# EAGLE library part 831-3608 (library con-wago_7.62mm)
Serie 831, Stiftleiste (für Leiterplatten) mit geraden Einlötstiften / Series 831, Male header (for PCBs) with straight solder pins Polzahl / Pole No.: 8 Bemessungsspannung / Rated Voltage: 630 V Nennstrom / Nominal Current: 41 A Lötstiftlänge: / Solder Pin Length: 4 mm Farbe / Color: lichtgrau / light gray Stand: 01.01.2012. Die jeweils aktuellen Daten zu diesem Artikel finden Sie in unserem Produktkatalog, den Sie unter www.wago.com einsehen können. As of: 01/01/2012. Please find the newest data for this article in our product catalogue, which can be viewed under www.wago.com.
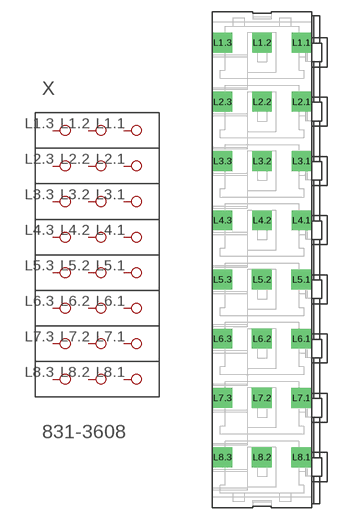
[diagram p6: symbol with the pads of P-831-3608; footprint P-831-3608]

Designator prefix X

## 831-3608  [P-831-3608]
L1.1  D
L1.2  SSS
L1.3  FDF
L2.1  X
L2.2  GGG
L2.3  SDF
L3.1  V
L3.2  C
L3.3  YYBB
L4.1  P4.1
L4.2  P4.2
L4.3  P4.3
L5.1  P5.1
L5.2  P5.2
L5.3  P5.3
L6.1  P6.1
L6.2  P6.2
L6.3  P6.3
L7.1  P7.1
L7.2  P7.2
L7.3  P7.3
L8.1  P8.1
L8.2  P8.2
L8.3  P8.3

## Footprint P-831-3608 (pad centres in mm)
drill 1.7 square: L1.1 4.08,27.94; L1.2 -1,27.94; L1.3 -6.08,27.94; L2.1 4.08,20.32; L2.2 -1,20.32; L2.3 -6.08,20.32; L3.1 4.08,12.7; L3.2 -1,12.7; L3.3 -6.08,12.7; L4.1 4.08,5.08; L4.2 -1,5.08; L4.3 -6.08,5.08; L5.1 4.07,-2.54; L5.2 -1.01,-2.54; L5.3 -6.09,-2.54; L6.1 4.07,-10.16; L6.2 -1.01,-10.16; L6.3 -6.09,-10.16; L7.1 4.07,-17.78; L7.2 -1.01,-17.78; L7.3 -6.09,-17.78; L8.1 4.07,-25.4; L8.2 -1.01,-25.4; L8.3 -6.09,-25.4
